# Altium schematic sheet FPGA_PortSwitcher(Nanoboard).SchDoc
size B; Organization: Altium Limited; Address1: L3, 12a Rodborough Rd; Address2: Frenchs Forest; Address3: NSW; Address4: Australia 2086
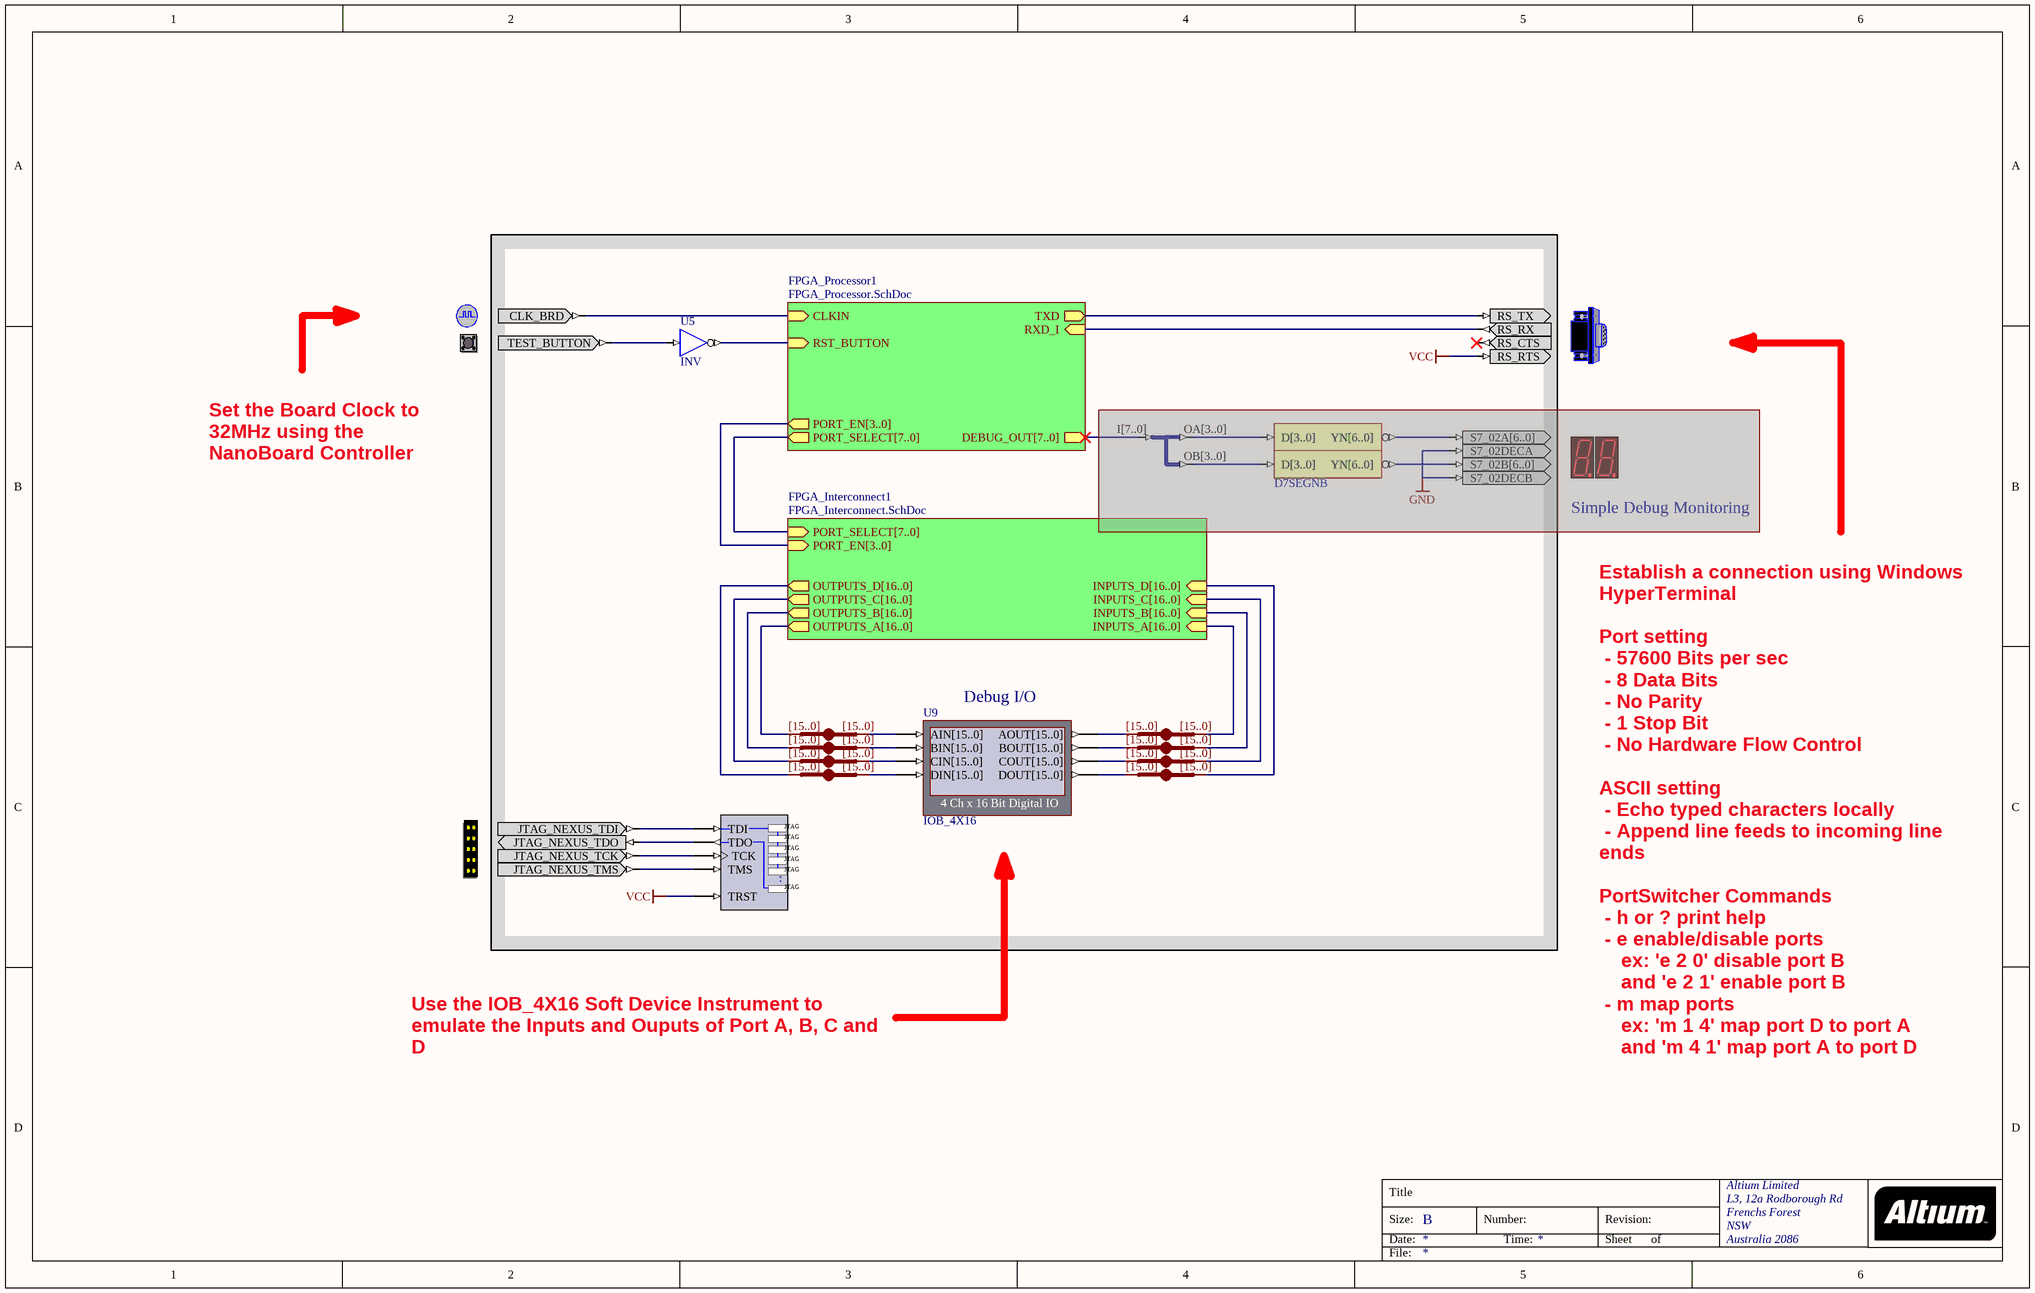
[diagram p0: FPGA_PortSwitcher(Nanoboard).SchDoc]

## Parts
(Parts that share a designator on the sheet are numbered #1, #2 ... from top to bottom, then left to right.)
?#1  CLOCK_BOARD  (value not drawn)
?#2  RS232CNTR  (value not drawn)
?#3  TEST_BUTTON  (value not drawn)
?#4  DUAL7SEGLEDUSERIO2  (value not drawn)  (masked out: inside a compile mask, not in the netlist)
?#5  NEXUS_JTAG_CONNECTOR  (value not drawn)
JB_S2  IndexA: [15..0]  (hidden comment: JB)
JB_S3  IndexA: [15..0]  (hidden comment: JB)
JB_S4  IndexA: [15..0]  (hidden comment: JB)
JB_S5  IndexA: [15..0]  (hidden comment: JB)
JB_S6  IndexA: [15..0]  (hidden comment: JB)
JB_S7  IndexA: [15..0]  (hidden comment: JB)
JB_S8  IndexA: [15..0]  (hidden comment: JB)
JB_S9  IndexA: [15..0]  (hidden comment: JB)
NEXUS_JTAG_PORT  NEXUS_JTAG_PORT  (value not drawn)
U5  INV
U6  D7SEGNB  (value not drawn)  (masked out: inside a compile mask, not in the netlist)
U7  D7SEGNB  (masked out: inside a compile mask, not in the netlist)
U8  J8B_4B2  (value not drawn)  (masked out: inside a compile mask, not in the netlist)
U9  IOB_4X16

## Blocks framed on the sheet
Debug I/O: ?#1-?#5 JB_S2-JB_S9 NEXUS_JTAG_PORT U5-U9

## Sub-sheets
FPGA_Interconnect1 = FPGA_Interconnect.SchDoc: PORT_SELECT[7..0] (in), OUTPUTS_D[16..0] (out), OUTPUTS_C[16..0] (out), OUTPUTS_B[16..0] (out), OUTPUTS_A[16..0] (out), PORT_EN[3..0] (in), INPUTS_A[16..0] (in), INPUTS_B[16..0] (in), INPUTS_C[16..0] (in), INPUTS_D[16..0] (in)
FPGA_Processor1 = FPGA_Processor.SchDoc: TXD (out), RXD_I (in), CLKIN (in), RST_BUTTON (in), PORT_SELECT[7..0] (out), PORT_EN[3..0] (out), DEBUG_OUT[7..0] (out)

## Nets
VCC: ?#2.RS_RTS NEXUS_JTAG_PORT.TRST
Net?#1_CLK_BRD: ?#1.CLK_BRD ; sheet FPGA_Processor1/CLKIN
Net?#2_RS_RX: ?#2.RS_RX ; sheet FPGA_Processor1/RXD_I
Net?#2_RS_TX: ?#2.RS_TX ; sheet FPGA_Processor1/TXD
Net?#3_TEST_BUTTON: ?#3.TEST_BUTTON U5.I
Net?#5_JTAG_NEXUS_TCK: ?#5.JTAG_NEXUS_TCK NEXUS_JTAG_PORT.TCK
Net?#5_JTAG_NEXUS_TDI: ?#5.JTAG_NEXUS_TDI NEXUS_JTAG_PORT.TDI
Net?#5_JTAG_NEXUS_TDO: ?#5.JTAG_NEXUS_TDO NEXUS_JTAG_PORT.TDO
Net?#5_JTAG_NEXUS_TMS: ?#5.JTAG_NEXUS_TMS NEXUS_JTAG_PORT.TMS
NetU5_O: U5.O ; sheet FPGA_Processor1/RST_BUTTON

Not connected (* = marked no-connect by the designer): ?#2 RS_CTS*; JB_S2 A[0..0] B[0..0]; JB_S3 A[0..0] B[0..0]; JB_S4 A[0..0] B[0..0]; JB_S5 A[0..0] B[0..0]; JB_S6 A[0..0] B[0..0]; JB_S7 A[0..0] B[0..0]; JB_S8 A[0..0] B[0..0]; JB_S9 A[0..0] B[0..0]; U9 AIN[15..0] AOUT[15..0] BIN[15..0] BOUT[15..0] CIN[15..0] COUT[15..0] DIN[15..0] DOUT[15..0]

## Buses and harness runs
bus sheet FPGA_Interconnect1/PORT_EN[3..0] = sheet FPGA_Processor1/PORT_EN[3..0]
bus sheet FPGA_Interconnect1/PORT_SELECT[7..0] = sheet FPGA_Processor1/PORT_SELECT[7..0]

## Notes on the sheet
- Set the Board Clock to 32MHz using the NanoBoard Controller
- Simple Debug Monitoring
- Use the IOB_4X16 Soft Device Instrument to emulate the Inputs and Ouputs of Port A, B, C and D
- Establish a connection using Windows HyperTerminal
  Port setting
  - 57600 Bits per sec
  - 8 Data Bits
  - No Parity
  - 1 Stop Bit
  - No Hardware Flow Control
  ASCII setting
  - Echo typed characters locally
  - Append line feeds to incoming line ends
  PortSwitcher Commands
  - h or ? print help
  - e enable/disable ports
  ex: 'e 2 0' disable port B
  and 'e 2 1' enable port B
  - m map ports
  ex: 'm 1 4' map port D to port A
  and 'm 4 1' map port A to port D

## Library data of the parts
?#1 = CLOCK_BOARD: Global System Clock Supply; PortComponent: True
?#2 = RS232CNTR: DCE Serial Port Connector; PortComponent: True
?#3 = TEST_BUTTON: Test Button; PortComponent: True
?#4 = DUAL7SEGLEDUSERIO2: Dual 7-Segment LED; PortComponent: True
?#5 = NEXUS_JTAG_CONNECTOR: JTAG Port; PortComponent: True
JB_S2-JB_S9 = JB: System BUS Joiner; ArchiveName: GENERIC
NEXUS_JTAG_PORT = NEXUS_JTAG_PORT: Soft Nexus-Chain Connector; NEXUS_JTAG_CONNECTOR: True
U5 = INV: Inverter; ArchiveName: GENERIC
U6 U7 = D7SEGNB: 7-Segment-Display Decoder for Common-Anode LED (Active Low Output), Bus Version; ArchiveName: GENERIC
U8 = J8B_4B2: 1 x 8-bit input bus to 2 x 4-Bit output bus; ArchiveName: GENERIC
U9 = IOB_4X16: 4 Ch x 16 Bit Digital IO; NEXUS_CORE: Instrument; NEXUS_JTAG_DEVICE: True; NEXUS_JTAG_ORDER: 0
